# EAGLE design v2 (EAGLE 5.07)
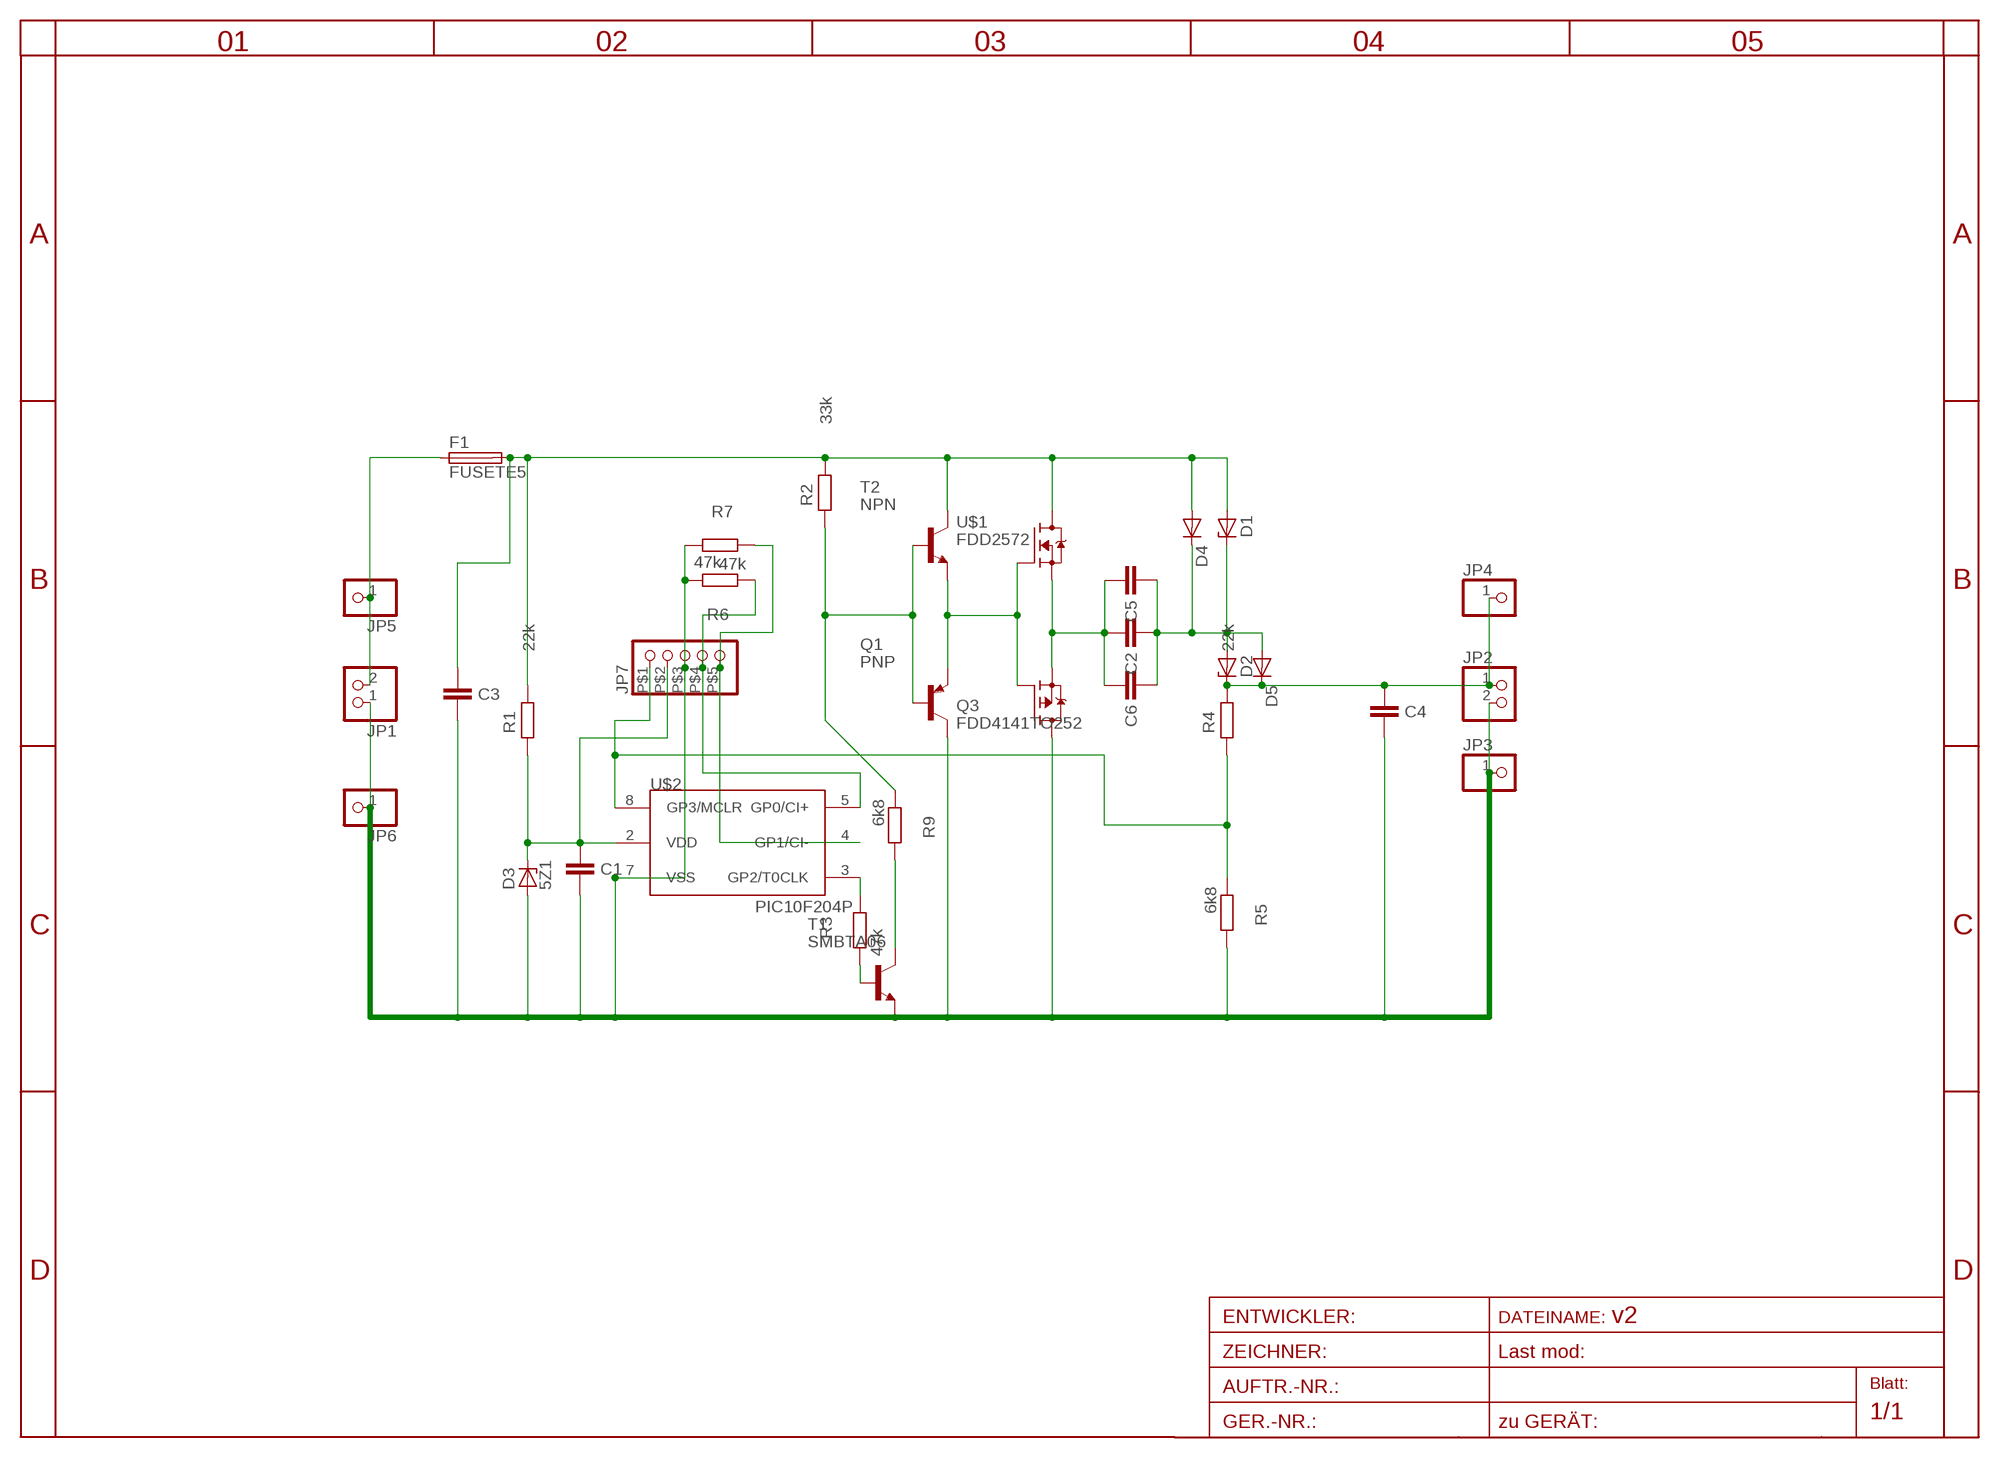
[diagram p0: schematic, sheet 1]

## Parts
C1  1u  C-EUC1206  [C1206]
C2  10n  C-EUC1206  [C1206]
C3  10n  C-EU050-075X075  [C050-075X075]
C4  10n  C-EU050-075X075  [C050-075X075]
C5  10n  C-EU050-025X075  [C050-025X075]
C6  10n  C-EUC1206  [C1206]
D1  ZENER-DIODESMB  [SMB]
D2  ZENER-DIODESMB  [SMB]
D3  5Z1  ZENER-DIODESOD80C  [SOD80C]
D4  DIODE-SMC  [SMC]
D5  DIODE-SMC  [SMC]
F1  FUSETE5  [TE5]
JP1  PINHD-1X2  [1X02X05]
JP2  PINHD-1X2  [1X02X05]
JP3  PINHD-1X11MM6  [1X1MM8]
JP4  PINHD-1X11MM6  [1X1MM8]
JP5  PINHD-1X11MM6  [1X1MM8]
JP6  PINHD-1X11MM6  [1X1MM8]
JP7  PINHD-1X5  [1X05SMD]
Q1  PNP  BC857ASMD  [SOT23-BEC]
Q3  FDD4141TO252  [TO252]
R1  22k  R-EU_R2010  [R2010]
R2  33k  R-EU_R2010  [R2010]
R3  47k  R-EU_R1206  [R1206]
R4  22k  R-EU_R2010  [R2010]
R5  6k8  R-EU_R1206  [R1206]
R6  47k  R-EU_R0402  [R0402]
R7  47k  R-EU_R0402  [R0402]
R9  6k8  R-EU_R1206  [R1206]
T1  SMBTA06  BC846  [SOT23]
T2  NPN  BC846  [SOT23]
U$1  FDD2572  [TO252]
U$2  PIC10F204P  [DIL8]

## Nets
BB: Q1.E Q3.1(G) T2.2(E) U$1.1(G)
EE: C2.1 C5.1 C6.1 Q3.2(S) U$1.2(S)
N$1: C1.2 D3.C JP7.P$2 R1.2 U$2.2(VDD)
N$2: R9.2 T1.3(C)
N$3: R3.2 U$2.3(GP2/T0CLK)
N$4: R3.1 T1.1(B)
N$5: JP7.P$1 R4.2 R5.1 U$2.8(GP3/MCLR)
N$6: Q1.B R2.2 R9.1 T2.1(B)
N$7: JP7.P$4 R6.1 U$2.5(GP0/CI+)
N$8: JP7.P$5 R7.2 U$2.4(GP1/CI-)
V+IN: F1.1 JP1.2 JP5.1
V-: C1.1 C3.1 C4.1 D3.A JP1.1 JP2.2 JP3.1 JP6.1 JP7.P$3 Q1.C Q3.3(D) R5.2 R6.2 R7.1 T1.2(E) U$2.7(VSS)
VFUS: C3.2 D1.A D4.A F1.2 R1.1 R2.1 T2.3(C) U$1.3(D)
VMID: C2.2 C5.2 C6.2 D1.C D2.A D4.C D5.A
VOUT: C4.2 D2.C D5.C JP2.1 JP4.1 R4.1

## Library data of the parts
C1-C6 = rcl-2:C-EU: CAPACITOR, European symbol
D1-D3 = diode-1:ZENER-DIODE: Z-Diode
D4 D5 = diode-1:DIODE-: DIODE
F1 = fuse:FUSE: Fuse
JP1 JP2 = pinhead:PINHD-1X2: PIN HEADER
JP3-JP6 = pinhead:PINHD-1X1: PIN HEADER
JP7 = pinhead:PINHD-1X5: PIN HEADER
Q1 = transistor-pnp:BC857*: PNP Transistror
Q3 = transistor-fet:FDD4141: P-Channel PowerTrench® MOSFET Source: FDD4141.pdf
R1-R7 R9 = rcl-2:R-EU_: RESISTOR, European symbol
T1 T2 = transistor:BC846: NPN TRANSISTOR
U$1 = transistor-fet:FDD2572
U$2 = microchip-5:PIC10F2*: uPC nW 0,25/0,5k Program Flash memory Comparator

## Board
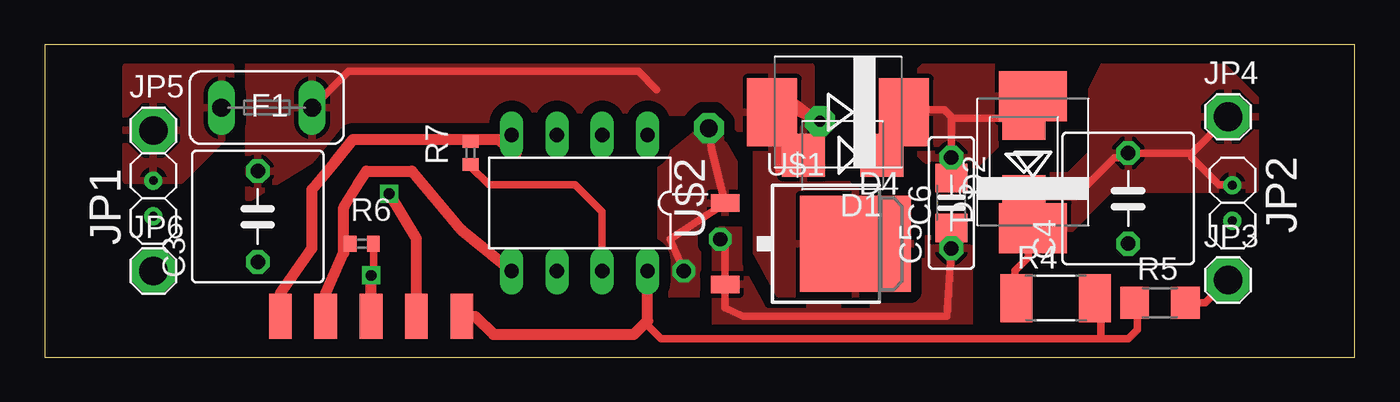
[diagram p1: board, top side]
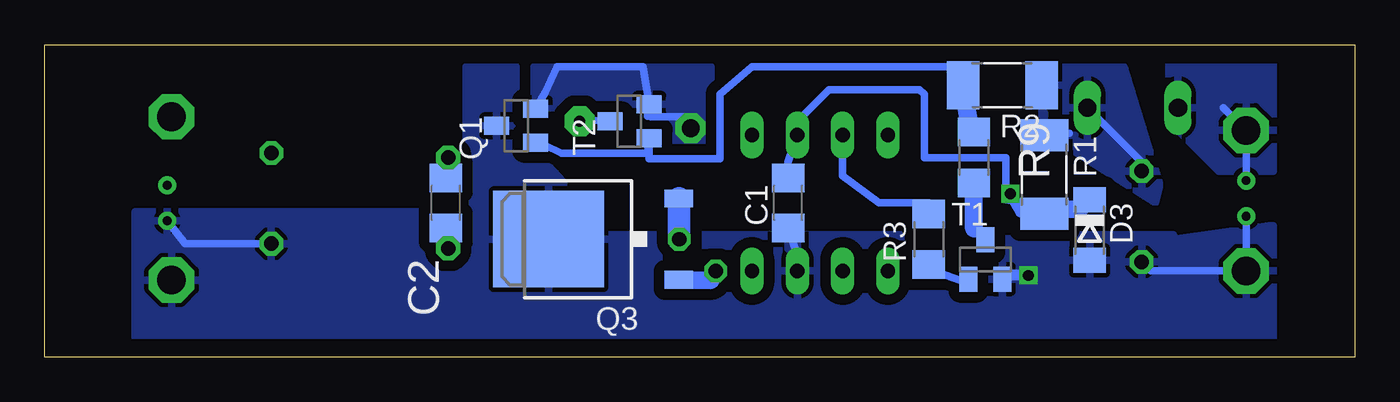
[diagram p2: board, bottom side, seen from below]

Size 73.41 x 17.5 mm. Coordinates in mm from the lower left corner, seen from the top.
Outline: 0,0 73.41,0 73.41,17.5 0,17.5 0,0
Copper layers (1*16): Top 0.035mm / dielectric 1.5mm / Bottom 0.035mm
Design rules "default": minimum track width 10mil, minimum drill 24mil, track to track 8mil, track to pad 8mil, pad to pad 8mil, via to via 8mil, smd to smd 8mil, copper to edge 40mil, drill to drill 8mil, minimum pad ring 10mil, minimum via ring 8mil, stop-mask expansion 4mil, vias tented up to drill 0mil, thermal gap 10mil

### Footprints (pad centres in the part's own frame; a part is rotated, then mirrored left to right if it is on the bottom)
C1206 = smd 1.6 x 1.8: 1 -1.4,0; 2 1.4,0
C050-075X075 = drill 0.813 octagon: 1 -2.54,0; 2 2.54,0
C050-025X075 = drill 0.813 octagon: 1 -2.54,0; 2 2.54,0
SMB = smd 2.4 x 2.4: A 2.2,0; C -2.2,0
SOD80C = smd 1.4 x 1.8: A 1.7,0; C -1.7,0
SMC = smd 2.8 x 3.8: A 3.7,0; C -3.7,0
TE5 = drill 1.016 long: 1 -2.54,0; 2 2.54,0
1X02X05 = drill 0.5 pad 0.813 round: 1 -1,0; 2 1,0
1X1MM8 = drill 1.6 pad 2.54 octagon: 1 0,0
1X05SMD = smd 1.27 x 2.54: P$1 -5.08,0; P$2 -2.54,0; P$3 0,0; P$4 2.54,0; P$5 5.08,0
SOT23-BEC = smd 1 x 1.4: B -0.95,-1.1; C 0,1.1; E 0.95,-1.1
TO252 = smd 1 x 1.6: 1 -2.28,-4.8; 2 2.28,-4.8 | smd 5.4 x 6.2: 3 0,2.5
R2010 = smd 1.8 x 2.7: 1 -2.2,0; 2 2.2,0
R1206 = smd 1.6 x 1.803: 1 -1.422,0; 2 1.422,0
R0402 = smd 0.7 x 0.9: 1 -0.65,0; 2 0.65,0
SOT23 = smd 1 x 1.4: 1 -0.95,-1.1; 2 0.95,-1.1; 3 0,1.1
DIL8 = drill 0.8 long: 1 -3.81,-3.81; 2 -1.27,-3.81; 3 1.27,-3.81; 4 3.81,-3.81; 5 3.81,3.81; 6 1.27,3.81; 7 -1.27,3.81; 8 -3.81,3.81

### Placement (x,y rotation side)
C1  31.75,8.64 90 bottom
C2  50.93,8.64 90 bottom
C3  11.94,7.87 90 top
C4  60.71,8.89 90 top
C5  50.8,8.64 90 top
C6  50.8,8.64 90 top
D1  44.7,11.3 180 top
D2  54.86,11.18 90 top
D3  14.86,7.11 270 bottom
D4  44.45,13.72 180 top
D5  55.37,10.92 90 top
F1  12.45,13.97 0 top
JP1  6.1,8.89 90 top
JP2  66.55,8.64 270 top
JP3  66.29,4.32 0 top
JP4  66.29,13.46 0 top
JP5  6.1,12.7 0 top
JP6  6.1,4.83 0 top
JP7  18.29,2.29 180 top
Q1  46.99,12.95 90 bottom
Q3  42.67,6.6 90 bottom
R1  17.4,10.22 270 bottom
R2  19.75,15.22 180 bottom
R3  23.88,6.6 90 bottom
R4  56.64,3.3 0 top
R5  62.48,3.05 0 top
R6  17.78,6.35 0 top
R7  23.88,11.43 90 top
R9  21.34,11.18 270 bottom
T1  20.7,5.46 0 bottom
T2  40.64,13.21 90 bottom
U$1  42.93,6.35 270 top
U$2  29.97,8.64 180 top

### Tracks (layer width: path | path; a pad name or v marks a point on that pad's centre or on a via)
BB  (via drill 0.8 pad 1.27, 1 pad 1.68)
  Top 0.406: v35.81,4.83 35.05,6.6 U$1.1 37.36,11.66 v37.21,12.83
  Bottom 0.406: 36.09,4.32 v35.81,4.83 | Q1.E 45.38,14.82 44.7,16.26 39.88,16.26 39.62,14.73 39.62,13.48 T2.2 39.47,13.46 37.34,13.46 v37.21,12.83
  Bottom 1.016: Q3.1 36.09,4.32
  pour Top (isolate 0.61, rank 3): 37.34,13.21 34.54,10.92 34.54,3.56 36.83,3.56 36.83,7.11 38.61,7.87 38.61,10.92
  pour Bottom (isolate 0.61, rank 3): 45.97,13.97 45.97,16.26 36.07,16.26 36.07,10.92 38.1,10.92 40.39,13.97
EE  (via drill 0.8 pad 1.27)
  Top 0.406: C5.1 50.55,2.29 39.12,2.29 38.13,2.77 U$1.2 38.12,6.6 v37.85,6.6
  Bottom 0.406: C5.1 50.8,7.11 C2.1 | v37.85,6.6 37.87,6.58
  Bottom 1.27: 37.87,6.58 Q3.2
  pour Top (isolate 0.61, rank 2): 50.29,6.86 51.31,6.86 51.82,6.35 51.82,1.78 51.56,1.52 37.59,1.52 37.59,6.6 37.85,7.11 39.12,7.11 39.37,6.86 39.37,5.08 41.15,3.3 49.02,3.3 49.02,6.35 49.28,6.6
N$1  (via drill 0.6)
  Top 0.61: JP7.P$2 20.83,6.6 v19.3,9.14
  Bottom 0.406: C1.2 31.75,10.92 U$2.2 31.24,13.21 29.46,14.99 24.38,14.99 24.13,14.73 24.13,11.18 19.56,11.18 19.56,8.81 18.29,8.56 R1.2 16.56,8.28 | 15.42,8.3 D3.C
  Bottom 0.61: v19.3,9.14 18.71,8.13 18.29,8.56
  Bottom 1.016: 16.56,8.28 15.42,8.3
N$2
  Bottom 0.406: T1.3 21.34,7.2
  Bottom 1.016: 21.34,7.2 R9.2
N$3
  Bottom 0.406: R3.2 23.62,7.87 23.88,8.64 26.67,8.64 28.7,10.16 U$2.3
N$4
  Bottom 0.406: R3.1 23.47,4.67 23.62,4.83 22.12,4.32 T1.1
N$5
  Top 0.406: 33.78,2.03 33.78,1.78 34.54,1.02 59.18,1.02 | 59.18,1.02 60.71,1.02 61.21,1.52 61.21,2.9 R5.1 | R4.2 59.18,3.3 59.18,1.02
  Top 0.61: JP7.P$1 24.13,2.29 25.15,1.27 33.02,1.27 33.78,2.03 U$2.8
N$6
  Bottom 0.406: Q1.B 45.38,11.85 44.45,11.43 39.62,11.43 39.62,11.41 T2.1 39.56,11.11 35.56,11.11 35.56,14.73 33.78,16.26 22.52,16.26 21.76,15.49 R2.2 | R9.1 21.59,12.19 21.5,12.61
  Bottom 1.016: 21.5,12.61 R2.2
N$7
  Top 0.406: 16.76,6.1 16.76,5.98 R6.1
  Top 0.61: JP7.P$4 15.75,3.56 16.76,5.84 16.76,6.1 16.76,8.38 17.53,9.65 18.03,10.41 20.57,10.41 23.37,7.11 U$2.5
N$8
  Top 0.406: R7.2 25.8,12.08 U$2.4
  Top 0.61: JP7.P$5 13.21,3.56 14.99,6.1 14.99,9.4 16.26,10.92 17.27,12.19 25.4,12.19 26.42,11.43 26.42,12.19 U$2.4
V+IN
  Bottom 0.406: 7.37,13.97 JP5.1 JP1.2
  pour Bottom (isolate 0.61, rank 3): 10.41,13.72 10.41,16.76 4.57,16.76 4.57,10.41 7.62,10.41 10.16,12.95
  pour Top (isolate 0.61, rank 3): 10.41,13.21 10.41,16.26 4.57,16.26 4.57,9.91 7.62,9.91 10.16,12.45
V-  (via drill 0.6)
  Top 0.406: R7.1 23.88,10.67 24.89,9.65 29.72,9.65 31.24,8.13 U$2.7 | R5.2 65.02,3.05 JP3.1 | R6.2 18.43,4.71 v18.29,4.57
  Top 0.61: JP7.P$3 v18.29,4.57
  Bottom 0.406: C3.1 11.43,4.83 JP6.1 JP1.1 | C4.1 65.53,6.35 JP2.2 | U$2.7 31.24,5.71 C1.1
  Bottom 0.61: v18.29,4.57 19.54,4.57 T1.2
  pour Bottom (isolate 0.61): 4.83,7.37 4.57,7.37 4.57,0 68.33,0 68.33,8.13 49.78,8.13 49.78,16.26 46.99,16.26 46.99,12.7 41.66,6.86 10.16,6.86 10.16,6.6
VFUS  (via drill 0.6 pad 1.68)
  Top 0.406: U$1.3 44.66,6.9 | 41.15,10.41 41.15,13.76 D1.A 41.23,14.06 v43.43,13.21 40.75,15.24 D4.A | 34.29,14.99 33.27,16 17.02,16 F1.2
  Bottom 0.406: C3.2 11.94,10.92 F1.2 | T2.3 43.26,13.29 v43.43,13.21 | R1.1 16,12.53
  pour Top (isolate 0.61): 11.43,16.51 42.93,16.26 42.93,10.67 43.43,9.65 46.74,9.65 48.51,8.38 48.51,3.56 41.15,3.56 39.88,5.84 39.88,11.94 37.85,13.72 34.29,13.72 33.27,11.68 16,11.68 11.43,8.89
  pour Bottom (isolate 0.61, rank 3): 11.18,8.64 16,11.68 18.03,11.68 18.03,16.26 12.95,16.26 10.92,9.65
VMID
  Top 0.406: D1.C 47.75,13.84 | 47.75,13.84 50.42,13.84 50.8,13.46 | 50.8,13.46 C5.2 | 50.8,13.46 50.89,13.38 D2.A 54.86,13.72 55.88,14.73 55.48,14.73 D5.A | D4.C 47.9,13.99 47.75,13.84
  Bottom 0.406: C5.2 50.93,11.18 C2.2
  pour Top: 49.02,15.49 49.02,16 49.28,16.26 53.59,16.26 54.1,15.75 54.1,12.7 52.07,10.67 50.04,10.67 49.78,10.67 49.02,11.43
VOUT
  Top 0.406: 55.37,8.98 D2.C | 55.37,8.98 57.74,8.98 59.94,11.18 60.45,11.18 C4.2 64.26,11.43 | 64.26,11.43 JP4.1 | 55.37,8.98 D5.C 55.37,6.86 55.12,6.6 55.12,5.59 54.36,4.83 54.36,3.39 R4.1 54.36,3.3 | 64.26,11.43 64.26,11.18 65.79,9.65 66.29,9.65 JP2.1
  pour Top: 65.53,16.76 67.82,14.48 67.82,9.4 59.69,9.4 56.9,6.6 55.12,6.6 54.86,6.86 54.86,9.4 55.63,10.16 57.4,10.16 58.67,11.43 58.67,14.99 59.44,16.51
